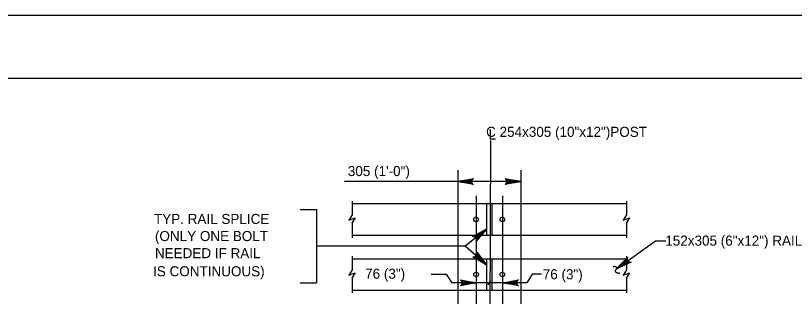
# Model space of a CAD drawing. Extents: x 0 to 36.3, y -66 to 0.
# Drawn here: x 11.08 to 20.36, y -3.35 to 0 of the extents above; entities that cross this region are included whole.
import ezdxf

# ---------------------------------------------------------------- set-up
doc = ezdxf.new("R2010")
doc.units = 0
for name, color, linetype in [('1', 7, 'Continuous'), ('2', 7, 'Continuous'), ('3', 7, 'Continuous'), ('63', 7, 'Continuous')]:
    doc.layers.add(name, color=color, linetype=linetype)

msp = doc.modelspace()

# ---------------------------------------------------------------- linework, layer by layer
at = {"layer": '1'}
msp.add_lwpolyline([(1.75, -21.25), (33.25, -21.25), (33.25, -0.75), (1.75, -0.75)], close=True, dxfattribs=at)
at = {"layer": '2'}
for p, q in [((15.0902, -2.2106), (15.0902, -2.3762)), ((18.3565, -2.2106), (18.3565, -2.3762)), ((15.0902, -2.2418), (18.3565, -2.2418)), ((16.3484, -2.2418), (16.3484, -2.6168)), ((16.6922, -2.2418), (16.6922, -2.6168)), ((16.7547, -2.2418), (16.7547, -2.6168)), ((17.0984, -2.2418), (17.0984, -2.6168)), ((15.0902, -2.3762), (15.053, -2.4382)), ((15.053, -2.4382), (15.1273, -2.4103)), ((15.1273, -2.4103), (15.0902, -2.466)), ((18.3565, -2.3762), (18.3193, -2.4382)), ((18.3193, -2.4382), (18.3935, -2.4103)), ((18.3935, -2.4103), (18.3565, -2.466)), ((15.0902, -2.466), (15.0902, -2.6481)), ((18.3565, -2.466), (18.3565, -2.6481)), ((15.0902, -2.6168), (18.3565, -2.6168)), ((16.3484, -2.6168), (16.3484, -2.8981)), ((17.0984, -2.6168), (17.0984, -2.8981)), ((15.0902, -2.8668), (15.0902, -3.0325)), ((18.3565, -2.8668), (18.3565, -3.0325)), ((15.0902, -2.8981), (18.3565, -2.8981)), ((16.3484, -2.8981), (16.3484, -3.2731)), ((16.6922, -2.8981), (16.6922, -3.2731)), ((16.7547, -2.8981), (16.7547, -3.2731)), ((17.0984, -2.8981), (17.0984, -3.2731)), ((15.0902, -3.0325), (15.053, -3.0944)), ((18.3565, -3.0325), (18.3193, -3.0944)), ((15.053, -3.0944), (15.1273, -3.0666)), ((15.1273, -3.0666), (15.0902, -3.1222)), ((15.0902, -3.1222), (15.0902, -3.3043)), ((18.3193, -3.0944), (18.3935, -3.0666)), ((18.3935, -3.0666), (18.3565, -3.1222)), ((18.3565, -3.1222), (18.3565, -3.3043)), ((15.0902, -3.2731), (18.3565, -3.2731)), ((16.3484, -3.2731), (16.3484, -3.6793)), ((17.0984, -3.2731), (17.0984, -3.6793))]:
    msp.add_line(p, q, dxfattribs=at)
for centre in [(16.5672, -2.4294), (16.8797, -2.4294), (16.5672, -3.0857), (16.8797, -3.0857)]:
    msp.add_circle(centre, 0.0273, dxfattribs=at)
at = {"layer": '3'}
for p, q in [((16.7368, -1.4887), (16.7234, -6.7043)), ((16.3484, -1.8425), (16.3484, -2.2418)), ((17.0984, -1.8425), (17.0984, -2.2418)), ((16.973, -1.9779), (15.0011, -1.9779)), ((16.5672, -2.1467), (16.5672, -4.994)), ((16.8797, -2.1467), (16.8797, -4.994)), ((14.4722, -2.3108), (14.6658, -2.3108)), ((14.6658, -2.3108), (14.6658, -3.1853)), ((16.6922, -2.5457), (16.4383, -2.7481)), ((18.2407, -3.0177), (18.7054, -2.6851)), ((18.7054, -2.6851), (18.8267, -2.6851)), ((16.4383, -2.7481), (14.6658, -2.7481)), ((16.6922, -2.9712), (16.4383, -2.7481)), ((16.0317, -3.0837), (16.2127, -3.0837)), ((16.2127, -3.0837), (16.2764, -3.1855)), ((17.234, -3.0837), (17.1703, -3.1855)), ((17.3441, -3.0837), (17.234, -3.0837)), ((14.4722, -3.1853), (14.6658, -3.1853)), ((17.1703, -3.1855), (16.2764, -3.1855)), ((16.7393, -3.1597), (16.7074, -3.2113))]:
    msp.add_line(p, q, dxfattribs=at)
for points in [[(16.3484, -1.9779), (16.5348, -1.943), (16.5205, -1.9529), (16.5131, -1.9654), (16.5109, -1.9779), (16.5131, -1.9904), (16.5205, -2.0029), (16.5348, -2.0128), (16.3484, -1.9779), (16.5205, -2.0029), (16.5131, -1.9904), (16.3484, -1.9779), (16.5109, -1.9779), (16.5131, -1.9654), (16.3484, -1.9779), (16.5205, -1.9529)], [(17.098, -1.9779), (16.9116, -2.0128), (16.9259, -2.0029), (16.9333, -1.9904), (16.9355, -1.9779), (16.9333, -1.9654), (16.9259, -1.9529), (16.9116, -1.943), (17.098, -1.9779), (16.9259, -1.9529), (16.9333, -1.9654), (17.098, -1.9779), (16.9355, -1.9779), (16.9333, -1.9904), (17.098, -1.9779), (16.9259, -2.0029)], [(16.6922, -2.5457), (16.5682, -2.6892), (16.5732, -2.6725), (16.5712, -2.6582), (16.5651, -2.647), (16.5557, -2.6386), (16.5421, -2.6334), (16.5246, -2.6346), (16.6922, -2.5457), (16.5421, -2.6334), (16.5557, -2.6386), (16.6922, -2.5457), (16.5651, -2.647), (16.5712, -2.6582), (16.6922, -2.5457), (16.5732, -2.6725)], [(16.6922, -2.9712), (16.5291, -2.8743), (16.5464, -2.8763), (16.5602, -2.8718), (16.5701, -2.8639), (16.5768, -2.8531), (16.5794, -2.8388), (16.5753, -2.8218), (16.6922, -2.9712), (16.5794, -2.8388), (16.5768, -2.8531), (16.6922, -2.9712), (16.5701, -2.8639), (16.5602, -2.8718), (16.6922, -2.9712), (16.5464, -2.8763)], [(18.2407, -3.0177), (18.372, -2.8808), (18.3661, -2.8973), (18.3673, -2.9118), (18.3729, -2.9232), (18.3819, -2.9321), (18.3952, -2.9379), (18.4127, -2.9377), (18.2407, -3.0177), (18.3952, -2.9379), (18.3819, -2.9321), (18.2407, -3.0177), (18.3729, -2.9232), (18.3673, -2.9118), (18.2407, -3.0177), (18.3661, -2.8973)], [(16.5672, -3.1855), (16.3807, -3.2204), (16.3951, -3.2105), (16.4025, -3.198), (16.4047, -3.1855), (16.4025, -3.173), (16.3951, -3.1605), (16.3807, -3.1506), (16.5672, -3.1855), (16.3951, -3.1605), (16.4025, -3.173), (16.5672, -3.1855), (16.4047, -3.1855), (16.4025, -3.198), (16.5672, -3.1855), (16.3951, -3.2105)], [(16.8842, -3.1855), (17.0706, -3.1506), (17.0562, -3.1605), (17.0488, -3.173), (17.0467, -3.1855), (17.0488, -3.198), (17.0562, -3.2105), (17.0706, -3.2204), (16.8842, -3.1855), (17.0562, -3.2105), (17.0488, -3.198), (16.8842, -3.1855), (17.0467, -3.1855), (17.0488, -3.173), (16.8842, -3.1855), (17.0562, -3.1605)]]:
    msp.add_lwpolyline(points, dxfattribs=at)
for points in [[(16.4734, -1.9988), (16.4734, -1.9571), (16.3484, -1.9779)], [(16.973, -1.9571), (16.973, -1.9988), (17.098, -1.9779)], [(16.5797, -2.6088), (16.6056, -2.6414), (16.6904, -2.5473)], [(16.6152, -2.8769), (16.5888, -2.907), (16.6922, -2.9712)]]:
    msp.add_lwpolyline(points, close=True, dxfattribs=at)
for centre, radius, start, end in [((18.2184, -3.031), 0.0394, 101.24, 119.22297), ((18.2155, -3.0166), 0.0248, 78.5013, 101.24), ((18.2088, -3.0496), 0.0585, 68.55376, 78.5013), ((18.2345, -3.0428), 0.0109, 141.43841, 177.1104), ((18.2414, -3.0431), 0.0178, 177.1104, 204.86978), ((18.2435, -3.0422), 0.0201, 204.86978, 233.05634), ((18.9365, -3.6024), 0.9087, 141.12339, 141.43841), ((21.1781, -5.4096), 3.788, 140.96911, 141.12339), ((18.2174, -3.0277), 0.0349, 55.672, 68.55376), ((18.2524, -3.0304), 0.0348, 233.05634, 254.40037), ((18.8554, -3.5267), 0.798, 140.21634, 140.9691), ((18.2166, -3.0289), 0.0364, 35.62317, 55.672), ((18.0357, -2.8441), 0.2687, 320.21634, 321.51358), ((18.2437, -3.0095), 0.00303, 321.51357, 35.62317), ((18.3169, -2.7991), 0.2749, 254.40037, 256.19123), ((18.3496, -2.666), 0.412, 256.19123, 257.65415), ((18.2869, -2.9526), 0.1187, 257.65415, 260.92719), ((18.3091, -2.8139), 0.2591, 260.92719, 263.14214)]:
    msp.add_arc(centre, radius, start, end, dxfattribs=at)
at = {"layer": '63'}
msp.add_lwpolyline([(0, -22), (34, -22), (34, 0), (0, 0)], close=True, dxfattribs=at)

# ---------------------------------------------------------------- texts
at = {"layer": '3'}
for s, p in [('C 254x305 (10"x12")POST', (16.6865, -1.4457)), ('L', (16.7165, -1.4776)), ('305 (1\'-0")', (15.04, -1.9131)), ('TYP. RAIL SPLICE', (12.7319, -2.484)), ('(ONLY ONE BOLT', (12.743, -2.6879)), ('152x305 (6"x12") RAIL', (18.8203, -2.7422)), ('NEEDED IF RAIL', (12.743, -2.8918)), ('IS CONTINUOUS)', (12.7208, -3.1077)), ('76 (3")', (15.2461, -3.1363)), ('76 (3")', (17.3609, -3.1433))]:
    msp.add_text(s, height=0.12, dxfattribs=at).set_placement(p)

doc.saveas('drawing.dxf')
